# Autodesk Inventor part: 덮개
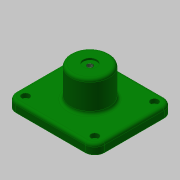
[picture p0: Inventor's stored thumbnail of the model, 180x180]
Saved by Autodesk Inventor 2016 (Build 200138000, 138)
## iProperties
Created: 2017-08
Part Number: 덮개
Material: 알루미늄 6061
Document SubType Name: Modeling
Designer: mduedu
Density: 1 g/cm^3
Appearance: 진녹색
Author: mduedu
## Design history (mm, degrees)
sketch "스케치1"
  geometry: L1 (46, -41)-(-46, -41); L2 (-46, -41)-(-46, 41); L3 (-46, 41)-(46, 41); L4 (46, 41)-(46, -41); 1 further point
  constraints: 8 end point, 2 parallel, 1 horizontal, 1 perpendicular
  dimensions: "d0" = 92 distance of L2.end L3.end; "d2" = 82 distance of L1.end L2.end; "d3" = 41 distance from line of L3 point (0, 0) (= 0.5 x d2); "d4" = 46 distance from line of point (0, 0) L4 (= 0.5 x d0)
extrude "돌출1" new body sketch "스케치1" distance "d5" = 10; taper "d6" = 0 deg
sketch "스케치2"
  geometry: C1 r 20 at (0, 0); 1 further point
  constraints: 1 centre point, 1 coincident
  dimensions: "d55" = 40 diameter of C1
extrude "돌출2" join sketch "스케치2" distance "d9" = 32; taper "d10" = 0 deg
sketch "스케치3"
  geometry: L1 (-26, -26)-(26, -26); L2 (26, -26)-(26, 26); L3 (26, 26)-(-26, 26); L4 (-26, 26)-(-26, -26); L5 (-26, -26)-(26, 26); L6 (26, -26)-(-26, 26); 1 further point
  constraints: 12 end point, 2 midpoint, 2 parallel, 2 perpendicular, 1 horizontal
  dimensions: "d11" = 52 distance of L3.end L2.end
extrude "돌출3" join sketch "스케치3" distance "d12" = 6; taper "d13" = 0 deg
sketch "스케치4"
  geometry: L1 (-17, -17)-(17, -17); L2 (17, -17)-(17, 17); L3 (17, 17)-(-17, 17); L4 (-17, 17)-(-17, -17); L5 (-17, -17)-(17, 17); L6 (17, -17)-(-17, 17); 1 further point
  constraints: 12 end point, 2 midpoint, 2 parallel, 2 perpendicular, 1 horizontal
  dimensions: "d14" = 34 distance of L2.end L3.end
extrude "돌출4" cut sketch "스케치4" distance "d16" = 5; taper "d17" = 0 deg
sketch "스케치5"
  geometry: C1 r 9 at (0, 0); 1 further point
  constraints: 1 centre point, 1 coincident
  dimensions: "d18" = 18 diameter of C1
extrude "돌출5" cut sketch "스케치5" distance "d19" = 34; taper "d20" = 0 deg
sketch "스케치6"
  geometry: 2 further points
  constraints: 1 coincident
hole "구멍1" sketch "스케치6" at (0, 0) diameter "d21" = 5.917; stored, may be unused: countersink angle "d25" = 90 deg, drill point angle "d27" = 118 deg; dims "d22" = 6, "d23" = 14, "d24" = 2, "d26" = 8
fillet "모깎기1" dims "d36" = 10
fillet "모깎기3" dims "d38" = 3
fillet "모깎기4" dims "d39" = 3
fillet "모깎기5" dims "d40" = 3
chamfer "모따기1" distance "d41" = 1; stored, may be unused: second distance "d42" = 2, angle "d43" = 45 deg
fillet "모깎기6" dims "d44" = 3
fillet "모깎기7" dims "d45" = 3
fillet "모깎기8" dims "d46" = 3
sketch "스케치8"
  geometry: A1 r 10 centre (-36, -31) between (-46, -31) and (-36, -41) reference; A2 r 10 centre (-36, 31) between (-36, 41) and (-46, 31) reference; A3 r 10 centre (36, 31) between (46, 31) and (36, 41) reference; A4 r 10 centre (36, -31) between (36, -41) and (46, -31) reference; 5 further points
  constraints: 4 coincident
sketch "스케치9"
  geometry: 4 further points
  constraints: 4 other
hole "구멍3" sketch "스케치9" at (-36, -31), (-36, 31), (36, 31), (36, -31) diameter "d48" = 4.5; stored, may be unused: countersink angle "d52" = 90 deg, drill point angle "d54" = 0 deg; dims "d49" = 6, "d50" = 8, "d51" = 4.6, "d53" = 8
node "솔리드1"
